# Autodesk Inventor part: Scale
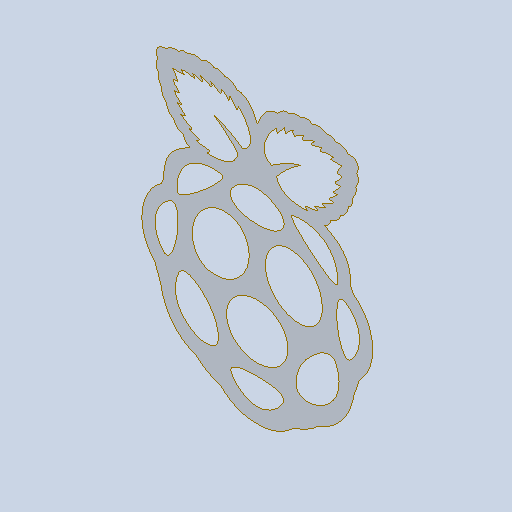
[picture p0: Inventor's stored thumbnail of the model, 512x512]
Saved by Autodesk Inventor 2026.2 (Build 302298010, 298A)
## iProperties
Created: 2026-10
Part Number: Scale
Material: Générique
Document SubType Name: Modeling
Designer: mel
Density: 1 g/cm^3
Appearance: Par défaut
Author: mel
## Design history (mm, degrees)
feature "Composite1"
body "Srf1"
